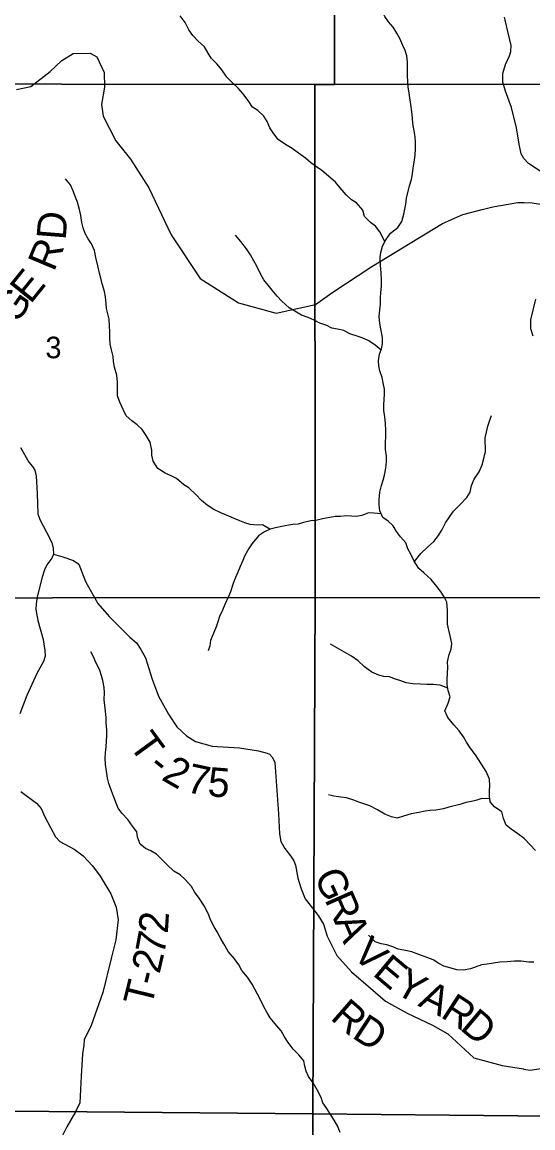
# Model space of a CAD drawing. Extents: x 2043100 to 2470832, y 443715 to 810583.
# Drawn here: x 2276946 to 2282180, y 595536 to 606876 of the extents above; entities that cross this region are included whole.
import ezdxf

# ---------------------------------------------------------------- set-up
doc = ezdxf.new("R2010")
doc.units = 0
for name, color, linetype in [('GM_X_Minor_River', 7, 'Continuous'), ('GM_X_Section', 7, 'Continuous'), ('GM_X_Section_Text', 7, 'Continuous'), ('GM_X_Township_Road', 7, 'Continuous'), ('GM_X_Township_Road_Text', 7, 'Continuous'), ('GM_X_Township_ROW', 7, 'Continuous')]:
    doc.layers.add(name, color=color, linetype=linetype)

msp = doc.modelspace()

# ---------------------------------------------------------------- linework, layer by layer
at = {"layer": 'GM_X_Minor_River'}
for points in [[(2280887, 606532), (2280870, 606584), (2280848, 606636), (2280815, 606708), (2280787, 606762), (2280748, 606824), (2280700, 606879), (2280663, 606933), (2280637, 606989), (2280594, 607057)], [(2280664, 604628), (2280612, 604724), (2280567, 604784), (2280517, 604821), (2280454, 604883), (2280438, 604949), (2280373, 605023), (2280321, 605052), (2280265, 605106), (2280206, 605176), (2280157, 605234), (2280085, 605297), (2280016, 605353), (2279952, 605398), (2279901, 605438), (2279849, 605480), (2279779, 605532), (2279714, 605579), (2279646, 605621), (2279569, 605672), (2279527, 605730), (2279484, 605792), (2279458, 605858), (2279423, 605910), (2279361, 605969), (2279308, 606005), (2279264, 606071), (2279207, 606145), (2279161, 606198), (2279100, 606258), (2279044, 606312), (2278991, 606388), (2278945, 606445), (2278882, 606507), (2278854, 606559), (2278815, 606623), (2278749, 606682), (2278696, 606738), (2278654, 606798), (2278617, 606872), (2278566, 606940)], [(2281300, 600084), (2281302, 600136), (2281309, 600261), (2281306, 600315), (2281322, 600391), (2281342, 600445), (2281349, 600505), (2281333, 600583), (2281318, 600639), (2281306, 600703), (2281305, 600843), (2281298, 600927), (2281272, 600983), (2281234, 601041), (2281181, 601105), (2281137, 601161), (2281062, 601228), (2281011, 601272), (2280963, 601348), (2280928, 601420), (2280900, 601476), (2280877, 601535), (2280823, 601599), (2280782, 601653), (2280748, 601711), (2280698, 601759), (2280641, 601796), (2280613, 601864), (2280606, 601926), (2280604, 601982), (2280611, 602056), (2280627, 602123), (2280645, 602177), (2280658, 602231), (2280674, 602301), (2280681, 602369), (2280679, 602425), (2280671, 602493), (2280668, 602557), (2280672, 602632), (2280673, 602696), (2280671, 602758), (2280662, 602828), (2280654, 602892), (2280652, 602950), (2280657, 603010), (2280661, 603060), (2280661, 603112), (2280646, 603178), (2280634, 603230), (2280613, 603300), (2280603, 603352), (2280598, 603404), (2280608, 603472), (2280630, 603526), (2280639, 603577), (2280639, 603641), (2280625, 603715), (2280612, 603787), (2280606, 603857), (2280613, 603927), (2280617, 603983), (2280620, 604047), (2280622, 604103), (2280628, 604169), (2280629, 604229), (2280625, 604305), (2280618, 604379), (2280614, 604464), (2280621, 604514), (2280639, 604580), (2280673, 604644), (2280722, 604711), (2280796, 604769), (2280836, 604831), (2280857, 604908), (2280867, 604958), (2280877, 605010), (2280886, 605070), (2280917, 605198), (2280935, 605263), (2280945, 605319), (2280954, 605377), (2280964, 605439), (2280974, 605513), (2280977, 605575), (2280977, 605645), (2280972, 605698), (2280962, 605762), (2280949, 605836), (2280945, 605894), (2280939, 605956), (2280930, 606032), (2280918, 606098), (2280911, 606148), (2280903, 606212), (2280898, 606262), (2280894, 606332), (2280894, 606400), (2280895, 606468), (2280887, 606532)], [(2279486, 601675), (2279409, 601720), (2279357, 601718), (2279284, 601725), (2279228, 601741), (2279176, 601761), (2279118, 601786), (2279063, 601808), (2278983, 601842), (2278912, 601877), (2278842, 601921), (2278784, 601970), (2278725, 602030), (2278654, 602100), (2278604, 602131), (2278529, 602195), (2278479, 602221), (2278411, 602250), (2278338, 602300), (2278288, 602372), (2278275, 602434), (2278275, 602488), (2278258, 602570), (2278218, 602636), (2278175, 602699), (2278125, 602747), (2278071, 602787), (2278014, 602837), (2277982, 602902), (2277947, 602978), (2277924, 603044), (2277922, 603134), (2277922, 603184), (2277915, 603254), (2277894, 603338), (2277884, 603396), (2277878, 603448), (2277861, 603516), (2277847, 603572), (2277844, 603632), (2277844, 603703), (2277842, 603759), (2277837, 603829), (2277825, 603885), (2277810, 603939), (2277808, 603989), (2277802, 604059), (2277789, 604115), (2277767, 604193), (2277752, 604251), (2277740, 604303), (2277721, 604377), (2277703, 604461), (2277688, 604533), (2277658, 604601), (2277623, 604654), (2277593, 604710), (2277572, 604766), (2277558, 604820), (2277547, 604894), (2277535, 604954), (2277512, 605028), (2277492, 605080), (2277466, 605154), (2277443, 605206), (2277391, 605270)], [(2280624, 603511), (2280563, 603564), (2280499, 603606), (2280431, 603637), (2280380, 603655), (2280304, 603679), (2280242, 603714), (2280179, 603728), (2280121, 603739), (2280067, 603765), (2279997, 603789), (2279940, 603820), (2279878, 603846), (2279808, 603872), (2279739, 603913), (2279683, 603947), (2279608, 604016), (2279558, 604066), (2279507, 604128), (2279467, 604180), (2279424, 604232), (2279392, 604287), (2279351, 604373), (2279321, 604427), (2279286, 604491), (2279246, 604551), (2279187, 604626), (2279133, 604692)], [(2280966, 601343), (2281031, 601428), (2281100, 601491), (2281166, 601551), (2281212, 601612), (2281249, 601672), (2281283, 601742), (2281321, 601795), (2281368, 601861), (2281432, 601924), (2281504, 602002), (2281536, 602056), (2281551, 602123), (2281579, 602189), (2281630, 602265), (2281660, 602336), (2281682, 602414), (2281693, 602474), (2281692, 602612), (2281704, 602670), (2281718, 602732), (2281739, 602793), (2281757, 602843)], [(2280626, 601832), (2280549, 601840), (2280495, 601843), (2280427, 601817), (2280374, 601805), (2280320, 601810), (2280268, 601812), (2280208, 601807), (2280154, 601805), (2280098, 601795), (2280024, 601782), (2279956, 601766), (2279904, 601761), (2279828, 601743), (2279774, 601727), (2279719, 601724), (2279657, 601714), (2279607, 601703), (2279543, 601689), (2279489, 601677), (2279431, 601650), (2279367, 601608), (2279302, 601529), (2279268, 601477), (2279228, 601407), (2279207, 601356), (2279181, 601292), (2279157, 601236), (2279124, 601158), (2279104, 601107), (2279082, 601035), (2279061, 600985), (2279025, 600903), (2279001, 600846), (2278970, 600782), (2278952, 600726), (2278934, 600674), (2278909, 600615), (2278877, 600535), (2278868, 600481), (2278852, 600429)], [(2281307, 600047), (2281230, 600078), (2281162, 600083), (2281094, 600083), (2281029, 600085), (2280951, 600090), (2280883, 600100), (2280827, 600121), (2280772, 600139), (2280710, 600161), (2280652, 600166), (2280602, 600178), (2280529, 600211), (2280453, 600263), (2280388, 600327), (2280320, 600374), (2280251, 600416), (2280177, 600457), (2280106, 600497)], [(2280204, 595489), (2280177, 595557), (2280145, 595615), (2280104, 595679), (2280070, 595735), (2280029, 595794), (2280011, 595848), (2279970, 595926), (2279928, 595998), (2279881, 596062), (2279857, 596116), (2279844, 596170), (2279832, 596222), (2279783, 596286), (2279725, 596345), (2279672, 596413), (2279636, 596469), (2279599, 596531), (2279557, 596584), (2279488, 596664), (2279452, 596722), (2279423, 596778), (2279397, 596834), (2279358, 596908), (2279330, 596959), (2279303, 597011), (2279255, 597081), (2279198, 597149), (2279168, 597207), (2279123, 597270), (2279059, 597344), (2279014, 597422), (2278977, 597490), (2278945, 597546), (2278915, 597598), (2278880, 597663), (2278852, 597735), (2278813, 597813), (2278762, 597893), (2278714, 597957), (2278683, 598011), (2278617, 598082), (2278564, 598130), (2278502, 598170), (2278431, 598233), (2278322, 598343), (2278266, 598376), (2278212, 598402), (2278155, 598444), (2278129, 598518), (2278120, 598572), (2278076, 598631), (2278029, 598697), (2277969, 598763), (2277930, 598815), (2277910, 598867), (2277883, 598939), (2277861, 598993), (2277836, 599068), (2277822, 599122), (2277811, 599194), (2277801, 599262), (2277797, 599327), (2277802, 599383), (2277808, 599445), (2277811, 599501), (2277815, 599559), (2277815, 599615), (2277808, 599689), (2277806, 599743), (2277797, 599839), (2277787, 599925), (2277790, 600001), (2277786, 600051), (2277773, 600123), (2277741, 600231), (2277706, 600301), (2277679, 600367), (2277649, 600419)], [(2282205, 598382), (2282151, 598440), (2282092, 598503), (2282024, 598553), (2281957, 598601), (2281907, 598642), (2281880, 598708), (2281862, 598776), (2281787, 598828), (2281741, 598880), (2281735, 598938), (2281736, 598992), (2281738, 599044), (2281735, 599112), (2281701, 599190), (2281654, 599266), (2281593, 599361), (2281537, 599435), (2281500, 599491), (2281470, 599547), (2281425, 599609), (2281369, 599670), (2281308, 599744), (2281276, 599814), (2281313, 599890), (2281331, 599956), (2281312, 600022), (2281300, 600084)], [(2281738, 598909), (2281657, 598915), (2281605, 598897), (2281552, 598884), (2281494, 598872), (2281432, 598854), (2281320, 598825), (2281264, 598808), (2281186, 598794), (2281128, 598790), (2281076, 598783), (2281010, 598771), (2280932, 598756), (2280854, 598734), (2280790, 598713), (2280730, 598725), (2280663, 598754), (2280589, 598798), (2280510, 598838), (2280448, 598859), (2280396, 598875), (2280346, 598897), (2280271, 598922), (2280211, 598926), (2280141, 598937), (2280087, 598953)], [(2282189, 597234), (2282137, 597236), (2282060, 597246), (2281990, 597245), (2281916, 597239), (2281840, 597236), (2281712, 597215), (2281654, 597207), (2281590, 597184), (2281540, 597168), (2281470, 597152), (2281399, 597157), (2281343, 597173), (2281269, 597194), (2281217, 597222), (2281158, 597260), (2281102, 597281), (2281012, 597313), (2280939, 597342), (2280859, 597358), (2280801, 597370), (2280744, 597393), (2280684, 597413), (2280626, 597422), (2280564, 597444), (2280497, 597512)]]:
    msp.add_lwpolyline(points, dxfattribs=at)
at = {"layer": 'GM_X_Section'}
for points in [[(2280143, 611576), (2280148, 606236), (2279944, 606237), (2274752, 606244), (2274805, 611595)], [(2285545, 611578), (2285539, 606241), (2280148, 606236), (2280143, 611576)], [(2274600, 606242), (2274752, 606244), (2279944, 606237), (2279948, 600975), (2274562, 600970)], [(2279944, 606237), (2280148, 606236), (2285539, 606241), (2285535, 600971), (2279948, 600975)], [(2274562, 600970), (2279948, 600975), (2279924, 595679), (2274515, 595729)], [(2285535, 600971), (2285527, 595624), (2279924, 595679), (2279948, 600975)], [(2274515, 595729), (2279924, 595679), (2279931, 590350), (2274466, 590370)], [(2285527, 595624), (2285489, 590369), (2279931, 590350), (2279924, 595679)]]:
    msp.add_lwpolyline(points, close=True, dxfattribs=at)
at = {"layer": 'GM_X_Township_Road'}
for points in [[(2282357, 605280), (2282136, 605427), (2282088, 605476), (2282061, 605524), (2282038, 605626), (2282011, 605791), (2281960, 605999), (2281898, 606169), (2281871, 606261), (2281873, 606349), (2281900, 606441), (2281939, 606532), (2281953, 606576), (2281957, 606638), (2281924, 606780), (2281890, 606926)], [(2282184, 603655), (2282159, 603731), (2282160, 603823), (2282209, 604034)], [(2276930, 602512), (2277015, 602364), (2277052, 602320), (2277078, 602280), (2277091, 602220), (2277100, 602042), (2277106, 601834), (2277128, 601774), (2277195, 601646), (2277250, 601540), (2277266, 601480), (2277267, 601420), (2277249, 601380), (2277200, 601311), (2277174, 601259), (2277151, 601184), (2277102, 600982), (2277089, 600911), (2277087, 600851), (2277108, 600741), (2277161, 600543), (2277178, 600431), (2277181, 600373), (2277165, 600319), (2277098, 600196), (2276994, 599969), (2276923, 599784)], [(2277267, 601420), (2277365, 601393), (2277474, 601355), (2277526, 601316), (2277597, 601138), (2277723, 600914), (2277838, 600781), (2278050, 600570), (2278119, 600509), (2278163, 600443), (2278210, 600357), (2278280, 600139), (2278345, 599963), (2278445, 599778), (2278532, 599648), (2278631, 599556), (2278723, 599499), (2278894, 599452), (2279174, 599434), (2279369, 599404), (2279457, 599379), (2279481, 599367), (2279513, 599335), (2279534, 599283), (2279551, 599091), (2279572, 598756), (2279583, 598552), (2279596, 598472), (2279637, 598400), (2279695, 598326), (2279732, 598276), (2279748, 598230), (2279773, 598096), (2279804, 597988), (2279845, 597886), (2279920, 597791), (2279978, 597713), (2280033, 597625), (2280072, 597501), (2280170, 597304), (2280321, 597136), (2280517, 596968), (2280670, 596834), (2280893, 596714), (2281150, 596590), (2281307, 596501), (2281575, 596256), (2281866, 596176), (2282084, 596140)], [(2276933, 598986), (2277094, 598867), (2277141, 598813), (2277179, 598725), (2277236, 598616), (2277289, 598520), (2277331, 598472), (2277478, 598395), (2277573, 598326), (2277666, 598224), (2277745, 598118), (2277856, 597935), (2277909, 597799), (2277932, 597669), (2277906, 597466), (2277859, 597273), (2277772, 596926), (2277654, 596586), (2277581, 596439), (2277578, 596385), (2277564, 596295), (2277550, 596068), (2277536, 595792), (2277493, 595701), (2277406, 595548), (2277343, 595423)]]:
    msp.add_lwpolyline(points, dxfattribs=at)
at = {"layer": 'GM_X_Township_ROW'}
for points in [[(2276890, 606184), (2277036, 606217), (2277233, 606371), (2277354, 606484), (2277470, 606555), (2277642, 606558), (2277711, 606519), (2277786, 606361), (2277789, 606209), (2277760, 606030), (2277775, 605912), (2277905, 605660), (2278057, 605469), (2278243, 605176), (2278475, 604695), (2278769, 604248), (2279165, 603996), (2279549, 603891), (2279953, 603980), (2280120, 604100), (2280531, 604371), (2281252, 604812), (2281463, 604904), (2281659, 604954), (2281771, 604981), (2282025, 605025), (2282089, 605027), (2282173, 605022), (2282279, 605007)], [(2282084, 596140), (2282086, 596139), (2282151, 596128), (2282461, 596175), (2282647, 596261), (2282779, 596500), (2282961, 596834), (2283063, 597058), (2283248, 597264), (2283375, 597337), (2283788, 597598), (2284135, 597798), (2284347, 597821), (2284803, 597893)]]:
    msp.add_lwpolyline(points, dxfattribs=at)

# ---------------------------------------------------------------- texts
at = {"layer": 'GM_X_Section_Text'}
msp.add_text('3', height=221, rotation=0, dxfattribs=at).set_placement((2277185, 603429))
at = {"layer": 'GM_X_Township_Road_Text'}
for s, rotation, p in [('D', 85.5031, (2277392, 604636)), ('R', 67.2956, (2277272, 604308)), ('E', 51.0872, (2277032, 603977)), ('G', 54.8782, (2276884, 603766)), ('T', 306.2167, (2278033, 599460)), ('2', 330.3363, (2278363, 599111)), ('-', 321.0216, (2278224, 599218)), ('7', 347.887, (2278617, 598984)), ('5', 355.3674, (2278840, 598939)), ('G', 294.4777, (2279933, 598119)), ('R', 293.7695, (2280042, 597880)), ('2', 86.554, (2278439, 597524)), ('A', 293.2024, (2280141, 597655)), ('7', 79.2384, (2278399, 597301)), ('V', 316.4383, (2280320, 597304)), ('2', 76.8815, (2278354, 597108)), ('E', 319.926, (2280527, 597109)), ('Y', 330.3605, (2280747, 596930)), ('T', 76.182, (2278271, 596767)), ('-', 76.3258, (2278324, 596985)), ('A', 333.8005, (2280994, 596791)), ('R', 319.027, (2280095, 596656)), ('R', 327.0753, (2281223, 596679)), ('D', 320.0111, (2281422, 596551)), ('D', 326.7801, (2280315, 596468))]:
    msp.add_text(s, height=300, rotation=rotation, dxfattribs=at).set_placement(p)

doc.saveas('drawing.dxf')
